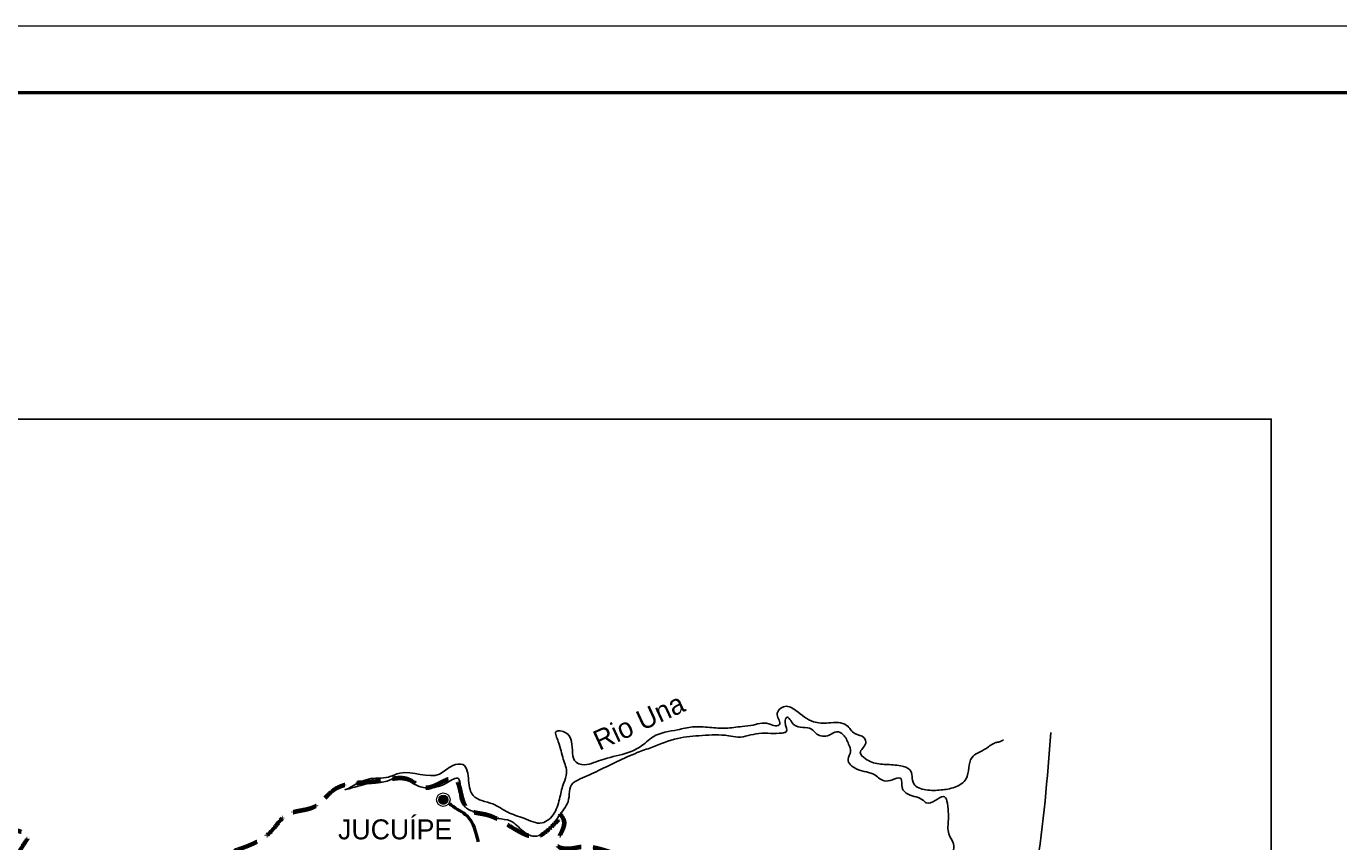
# Model space of a CAD drawing. Extents: x 512883 to 1063249, y 8784064 to 9081064.
# Drawn here: x 851806 to 950481, y 9019768 to 9081064 of the extents above; entities that cross this region are included whole.
import ezdxf

# ---------------------------------------------------------------- set-up
doc = ezdxf.new("R2010")
doc.units = 0
doc.header["$LTSCALE"] = 600
doc.linetypes.add('MEDIUM_DASHED', pattern=[4.5, 3, -1.5])
for name, color, linetype, lineweight in [('1', 7, 'Continuous', 25), ('10', 7, 'Continuous', 53), ('13', 7, 'Continuous', 90), ('3', 7, 'Continuous', 25), ('5', 7, 'Continuous', 13), ('60', 7, 'Continuous', 25), ('7', 7, 'Continuous', 13)]:
    doc.layers.add(name, color=color, linetype=linetype, lineweight=lineweight)

msp = doc.modelspace()

# ---------------------------------------------------------------- linework, layer by layer
at = {"layer": '1', "lineweight": 13}
for points in [[(512883.1, 8784063.9), (1063248.6, 8784063.9), (1063248.6, 9081063.9), (512883.1, 9081063.9)], [(537883.1, 9076063.9), (1058248.6, 9076063.9), (1058248.6, 8789063.9), (537883.1, 8789063.9)]]:
    msp.add_lwpolyline(points, close=True, dxfattribs=at)
at = {"layer": '1', "lineweight": 53}
msp.add_lwpolyline([(537883.1, 8789063.9), (1058248.6, 8789063.9), (1058248.6, 9076063.9), (537883.1, 9076063.9)], close=True, dxfattribs=at)
at = {"layer": '1'}
msp.add_lwpolyline([(566926, 9051542.3), (945407.2, 9051542.3), (945407.2, 8818457.9), (566926, 8818457.9)], close=True, dxfattribs=at)
at = {"layer": '10', "lineweight": 25}
msp.add_lwpolyline([(537883.1, 9076063.9), (1058248.6, 9076063.9), (1058248.6, 8789063.9), (537883.1, 8789063.9)], close=True, dxfattribs=at)
at = {"layer": '10'}
msp.add_spline([(885798.3, 9019767.7), (884973.2, 9021685), (883758, 9022515.8), (883651.9, 9022605.9)], degree=3, dxfattribs=at)
at = {"layer": '13', "linetype": 'MEDIUM_DASHED', "lineweight": 70}
for points in [[(829197.7, 9014555.7), (831473.6, 9016400), (832666.2, 9017154.5), (834733.9, 9017369.9), (835640, 9019042.3), (836236.9, 9019586.8), (837561.8, 9019737.1), (838427.1, 9019635.6), (839749.4, 9020015.5), (840270.1, 9020184.1), (841903.2, 9019730.3), (843435.9, 9019255.3), (844202.6, 9018986.5), (845489.1, 9018969.8), (846564, 9019912.3), (847141.3, 9020415), (847503.1, 9020416.2), (848201.5, 9020877.5), (849137.8, 9021631.8), (849378.7, 9021653.5), (851009.8, 9020657.6), (851917.3, 9020333.2), (851204.2, 9018711.4), (851722.8, 9017284.2), (851463.5, 9016311.1), (851528.3, 9016051.6), (853343.4, 9016311.1), (853862, 9014494.6), (854510.2, 9013456.6), (856519.7, 9014819), (859436.7, 9015467.7), (863390.8, 9016246.2), (864298.3, 9017478.8), (865141, 9018062.7), (866956, 9018906), (870290.9, 9020619.3), (871354.3, 9021775.5), (873540.1, 9022444.2), (874876.6, 9023632.2), (878429.5, 9024355.4), (880633.5, 9024420.3), (881745.7, 9023840.8), (883985, 9024525.5), (884931.5, 9022281.3), (886399.3, 9021809.7), (890479.7, 9020270.3), (891416.2, 9021016.7), (892059.7, 9021678.2)], [(896159.6, 9018825.1), (893440.4, 9019354.2), (892436.9, 9019225.7), (891730.7, 9019473.9), (891903.7, 9020184), (892232, 9021395.4), (891946.9, 9021863.4)]]:
    msp.add_spline(points, degree=3, dxfattribs=at)
at = {"layer": '3'}
msp.add_lwpolyline([(537883.1, 9076063.9), (1058248.6, 9076063.9), (1058248.6, 8789063.9), (537883.1, 8789063.9)], close=True, dxfattribs=at)
at = {"layer": '5'}
for p, q in [((882828.3, 9022937.2), (883493.1, 9022937.2)), ((882828.9, 9022907.2), (883492.8, 9022907.2)), ((882830.4, 9022967.2), (883491, 9022967.2)), ((882831.9, 9022877.2), (883489.5, 9022877.2)), ((882835.2, 9022997.2), (883486.2, 9022997.2)), ((882843.3, 9023027.2), (883478.1, 9023027.2)), ((882854.1, 9023057.2), (883467.3, 9023057.5)), ((882868.5, 9023087.2), (883453.2, 9023087.2)), ((882886.8, 9023117.2), (883434.9, 9023117.2)), ((882910.8, 9023147.2), (883411.2, 9023147.2)), ((882939.9, 9023177.2), (883381.5, 9023177.2)), ((882979.5, 9023207.2), (883341.9, 9023207.2)), ((883036.8, 9023237.2), (883284.6, 9023237.2)), ((882837.9, 9022847.2), (883483.5, 9022847.2)), ((882846.9, 9022817.2), (883474.5, 9022817.2)), ((882859.5, 9022787.2), (883462.2, 9022787.5)), ((882875.4, 9022757.2), (883446, 9022757.2)), ((882896.1, 9022727.2), (883425.6, 9022727.5)), ((882921.3, 9022696.9), (883400.4, 9022697.2)), ((882954.6, 9022667.2), (883366.8, 9022667.2)), ((882999.6, 9022637.2), (883321.8, 9022637.2)), ((883073.4, 9022607.2), (883247.7, 9022607.2))]:
    msp.add_line(p, q, dxfattribs=at)
for radius in [506.1, 332.9]:
    msp.add_circle((883160.8, 9022928.2), radius, dxfattribs=at)
at = {"layer": '60'}
for points in [[(875966.3, 9023742.7), (876845.3, 9024225.5), (877525.8, 9024478.1), (879031.6, 9024629.1), (879892.5, 9024924), (882868, 9024850.1), (883885.8, 9025500.3), (884628.7, 9025565.3), (885064, 9024377.3), (885172.1, 9023689), (885398, 9023251.5), (886872.3, 9022609.3), (888004.7, 9021986.9), (889215.7, 9021531.7), (890586.3, 9021181.4), (891502.7, 9021914.7), (891931.5, 9023126.5), (892221.1, 9024191.7), (892434.1, 9024922.8), (892181.4, 9025965.4), (891804.9, 9027299.7), (891635.8, 9028050.5), (892380.6, 9027948.5), (892879.8, 9026426.7), (893148.7, 9025739), (893572.6, 9025573.4), (895015.9, 9025911.9), (896839.5, 9026397.8), (897959.5, 9026902.2), (898936, 9027656.7), (900779.2, 9028184.3), (901902.4, 9028396.6), (903189.1, 9028359.1), (904395.7, 9028300.3), (905620.3, 9028429.5), (906463.2, 9028536.6), (907124.9, 9028684.8), (907789.2, 9028582.6), (908232.6, 9028479.7), (908412.5, 9028563.7), (908263.5, 9029314.5), (908839.4, 9029942.4), (909666.9, 9029632.1), (911002.8, 9028780.8), (912109.2, 9028700.9), (912872.7, 9028724.2), (913477.9, 9028517.5), (914107.9, 9027893.5), (914794.7, 9027582.7), (914919.9, 9027165.7), (914505.7, 9026454.8), (914872.3, 9026017.8), (915901.7, 9025624.6), (916987.9, 9025544.7), (917551.5, 9025463), (918238.1, 9025173.1), (918531, 9024130.6), (919440.5, 9023674.4), (920586.3, 9023657.3), (921609, 9023869.2), (922466.3, 9024498.1), (922890.9, 9026085.4), (923968.6, 9026777.6), (924687.3, 9027218.1), (924967.9, 9027281.6), (925287.9, 9027428.8)], [(875966.3, 9023742.7), (876845.3, 9024225.5), (877525.8, 9024478.1), (879031.6, 9024629.1), (879892.5, 9024924), (882868, 9024850.1), (883885.8, 9025500.3), (884628.7, 9025565.3), (885064, 9024377.3), (885172.1, 9023689), (885398, 9023251.5), (886872.3, 9022609.3), (888004.7, 9021986.9), (889215.7, 9021531.7), (890586.3, 9021181.4), (891502.7, 9021914.7), (891931.5, 9023126.5), (892221.1, 9024191.7), (892434.1, 9024922.8), (892181.4, 9025965.4), (891804.9, 9027299.7), (891635.8, 9028050.5), (892380.6, 9027948.5), (892879.8, 9026426.7), (893148.7, 9025739), (893572.6, 9025573.4), (895015.9, 9025911.9), (896839.5, 9026397.8), (897959.5, 9026902.2), (898936, 9027656.7), (900779.2, 9028184.3), (901902.4, 9028396.6), (903189.1, 9028359.1), (904395.7, 9028300.3), (905620.3, 9028429.5), (906463.2, 9028536.6), (907124.9, 9028684.8), (907789.2, 9028582.6), (908232.6, 9028479.7), (908412.5, 9028563.7), (908263.5, 9029314.5), (908839.4, 9029942.4), (909666.9, 9029632.1), (911002.8, 9028780.8), (912109.2, 9028700.9), (912872.7, 9028724.2), (913477.9, 9028517.5), (914107.9, 9027893.5), (914794.7, 9027582.7), (914919.9, 9027165.7), (914505.7, 9026454.8), (914872.3, 9026017.8), (915901.7, 9025624.6), (916987.9, 9025544.7), (917551.5, 9025463), (918238.1, 9025173.1), (918531, 9024130.6), (919440.5, 9023674.4), (920586.3, 9023657.3), (921609, 9023869.2), (922466.3, 9024498.1), (922890.9, 9026085.4), (923968.6, 9026777.6), (924687.3, 9027218.1), (924967.9, 9027281.6), (925287.9, 9027428.8)], [(921127.1, 9022010.4), (920752.4, 9023177.8), (919471.5, 9022693.7), (919268.6, 9022860), (918117.7, 9023336.3), (917650, 9023835.6), (917582.3, 9024503.2), (916418.4, 9024332.5), (915609.4, 9024789), (914258, 9025222.8), (913586.5, 9025971.9), (913781.2, 9026536), (913634.3, 9027099), (913224.5, 9027807.2), (912739.6, 9028035.1), (912159.5, 9027782.8), (911234.1, 9027863.3), (910848.1, 9028237.7), (909497.6, 9028588.1), (908989.1, 9029129.1), (908852.6, 9028753), (908941.1, 9028022.9), (908640.5, 9027938.4), (907776.5, 9027914.8), (906872.1, 9027911.8), (905307.5, 9027635.5), (904602.9, 9027737.6), (902613, 9027752), (900786.4, 9027537.4), (898824.2, 9026863.3), (897743.2, 9026463.3), (896223.2, 9025790.6), (894643.8, 9025034.2), (893284, 9024403.8), (892904.7, 9024173), (892538.3, 9022773.7), (891846.7, 9021707.2), (891432, 9021038), (889974.3, 9020177.7), (889166.2, 9020550.7), (888192.8, 9021340.6), (887266.2, 9021525.4), (886257.6, 9021856.1), (884906.2, 9022289.9), (884435.6, 9023039.7), (884425, 9023999.6), (884298.6, 9024520.9), (883418, 9024184.1), (882195.9, 9023825.4), (881794, 9023824.1), (880926.3, 9024134.3), (879634.7, 9024610.2), (878934.5, 9024315.7), (877950.4, 9024249.9), (876968.4, 9023996.3), (875826, 9023700.5), (875966.3, 9023742.7)], [(921127.1, 9022010.4), (920752.4, 9023177.8), (919471.5, 9022693.7), (919268.6, 9022860), (918117.7, 9023336.3), (917650, 9023835.6), (917582.3, 9024503.2), (916418.4, 9024332.5), (915609.4, 9024789), (914258, 9025222.8), (913586.5, 9025971.9), (913781.2, 9026536), (913634.3, 9027099), (913224.5, 9027807.2), (912739.6, 9028035.1), (912159.5, 9027782.8), (911234.1, 9027863.3), (910848.1, 9028237.7), (909497.6, 9028588.1), (908989.1, 9029129.1), (908852.6, 9028753), (908941.1, 9028022.9), (908640.5, 9027938.4), (907776.5, 9027914.8), (906872.1, 9027911.8), (905307.5, 9027635.5), (904602.9, 9027737.6), (902613, 9027752), (900786.4, 9027537.4), (898824.2, 9026863.3), (897743.2, 9026463.3), (896223.2, 9025790.6), (894643.8, 9025034.2), (893284, 9024403.8), (892904.7, 9024173), (892538.3, 9022773.7), (891846.7, 9021707.2), (891432, 9021038), (889974.3, 9020177.7), (889166.2, 9020550.7), (888192.8, 9021340.6), (887266.2, 9021525.4), (886257.6, 9021856.1), (884906.2, 9022289.9), (884435.6, 9023039.7), (884425, 9023999.6), (884298.6, 9024520.9), (883418, 9024184.1), (882195.9, 9023825.4), (881794, 9023824.1), (880926.3, 9024134.3), (879634.7, 9024610.2), (878934.5, 9024315.7), (877950.4, 9024249.9), (876968.4, 9023996.3), (875826, 9023700.5), (875966.3, 9023742.7)], [(928828.8, 9027989.5), (927727.3, 9017705.9), (905698.2, 8975836.8), (863108.4, 8926255), (823455.9, 8876673.2), (798489.5, 8846556.8), (787107.7, 8828193.2)], [(928828.8, 9027989.5), (927727.3, 9017705.9), (905698.2, 8975836.8), (863108.4, 8926255), (823455.9, 8876673.2), (798489.5, 8846556.8), (787107.7, 8828193.2)], [(901775.1, 8987223), (902699.2, 8987267.7), (903381.6, 8987353.4), (903745.9, 8987125), (904216, 8986417), (904742.9, 8986022.2), (904975.1, 8986836.8), (904846.2, 8987587.7), (905358.8, 8988486.7), (906193.7, 8989324.1), (906819.3, 8990912.1), (908413, 8994005.8), (909378, 8995803.6), (909823.6, 8997307.5), (910391.9, 8998624.1), (911240.2, 9000066.7), (912825.4, 9002116.9), (913573.4, 9003538.4), (914627.5, 9004543.5), (915816.5, 9006070.7), (916949.4, 9007222.1), (917364.1, 9007891.3), (917588.9, 9009373.6), (918101, 9010314.4), (918646, 9011923), (919238.3, 9012884.8), (919495.7, 9013240.4), (920353.7, 9013806.7), (920562, 9014955.1), (920543.8, 9016603.6), (920872.3, 9017794.2), (921207.5, 9018379.6), (921515.4, 9019611.8), (921165.5, 9020361.9), (921133.3, 9021447), (921127.1, 9022010.4)], [(901775.1, 8987223), (902699.2, 8987267.7), (903381.6, 8987353.4), (903745.9, 8987125), (904216, 8986417), (904742.9, 8986022.2), (904975.1, 8986836.8), (904846.2, 8987587.7), (905358.8, 8988486.7), (906193.7, 8989324.1), (906819.3, 8990912.1), (908413, 8994005.8), (909378, 8995803.6), (909823.6, 8997307.5), (910391.9, 8998624.1), (911240.2, 9000066.7), (912825.4, 9002116.9), (913573.4, 9003538.4), (914627.5, 9004543.5), (915816.5, 9006070.7), (916949.4, 9007222.1), (917364.1, 9007891.3), (917588.9, 9009373.6), (918101, 9010314.4), (918646, 9011923), (919238.3, 9012884.8), (919495.7, 9013240.4), (920353.7, 9013806.7), (920562, 9014955.1), (920543.8, 9016603.6), (920872.3, 9017794.2), (921207.5, 9018379.6), (921515.4, 9019611.8), (921165.5, 9020361.9), (921133.3, 9021447), (921127.1, 9022010.4)]]:
    msp.add_spline(points, degree=3, dxfattribs=at)
at = {"layer": '7', "lineweight": 25}
for points in [[(875966.3, 9023742.7), (876845.3, 9024225.5), (877525.8, 9024478.1), (879031.6, 9024629.1), (879892.5, 9024924), (882868, 9024850.1), (883885.8, 9025500.3), (884628.7, 9025565.3), (885064, 9024377.3), (885172.1, 9023689), (885398, 9023251.5), (886872.3, 9022609.3), (888004.7, 9021986.9), (889215.7, 9021531.7), (890586.3, 9021181.4), (891502.7, 9021914.7), (891931.5, 9023126.5), (892221.1, 9024191.7), (892434.1, 9024922.8), (892181.4, 9025965.4), (891804.9, 9027299.7), (891635.8, 9028050.5), (892380.6, 9027948.5), (892879.8, 9026426.7), (893148.7, 9025739), (893572.6, 9025573.4), (895015.9, 9025911.9), (896839.5, 9026397.8), (897959.5, 9026902.2), (898936, 9027656.7), (900779.2, 9028184.3), (901902.4, 9028396.6), (903189.1, 9028359.1), (904395.7, 9028300.3), (905620.3, 9028429.5), (906463.2, 9028536.6), (907124.9, 9028684.8), (907789.2, 9028582.6), (908232.6, 9028479.7), (908412.5, 9028563.7), (908263.5, 9029314.5), (908839.4, 9029942.4), (909666.9, 9029632.1), (911002.8, 9028780.8), (912109.2, 9028700.9), (912872.7, 9028724.2), (913477.9, 9028517.5), (914107.9, 9027893.5), (914794.7, 9027582.7), (914919.9, 9027165.7), (914505.7, 9026454.8), (914872.3, 9026017.8), (915901.7, 9025624.6), (916987.9, 9025544.7), (917551.5, 9025463), (918238.1, 9025173.1), (918531, 9024130.6), (919440.5, 9023674.4), (920586.3, 9023657.3), (921609, 9023869.2), (922466.3, 9024498.1), (922890.9, 9026085.4), (923968.6, 9026777.6), (924687.3, 9027218.1), (924967.9, 9027281.6), (925287.9, 9027428.8)], [(921127.1, 9022010.4), (920752.4, 9023177.8), (919471.5, 9022693.7), (919268.6, 9022860), (918117.7, 9023336.3), (917650, 9023835.6), (917582.3, 9024503.2), (916418.4, 9024332.5), (915609.4, 9024789), (914258, 9025222.8), (913586.5, 9025971.9), (913781.2, 9026536), (913634.3, 9027099), (913224.5, 9027807.2), (912739.6, 9028035.1), (912159.5, 9027782.8), (911234.1, 9027863.3), (910848.1, 9028237.7), (909497.6, 9028588.1), (908989.1, 9029129.1), (908852.6, 9028753), (908941.1, 9028022.9), (908640.5, 9027938.4), (907776.5, 9027914.8), (906872.1, 9027911.8), (905307.5, 9027635.5), (904602.9, 9027737.6), (902613, 9027752), (900786.4, 9027537.4), (898824.2, 9026863.3), (897743.2, 9026463.3), (896223.2, 9025790.6), (894643.8, 9025034.2), (893284, 9024403.8), (892904.7, 9024173), (892538.3, 9022773.7), (891846.7, 9021707.2), (891432, 9021038), (889974.3, 9020177.7), (889166.2, 9020550.7), (888192.8, 9021340.6), (887266.2, 9021525.4), (886257.6, 9021856.1), (884906.2, 9022289.9), (884435.6, 9023039.7), (884425, 9023999.6), (884298.6, 9024520.9), (883418, 9024184.1), (882195.9, 9023825.4), (881794, 9023824.1), (880926.3, 9024134.3), (879634.7, 9024610.2), (878934.5, 9024315.7), (877950.4, 9024249.9), (876968.4, 9023996.3), (875826, 9023700.5), (875966.3, 9023742.7)], [(901775.1, 8987223), (902699.2, 8987267.7), (903381.6, 8987353.4), (903745.9, 8987125), (904216, 8986417), (904742.9, 8986022.2), (904975.1, 8986836.8), (904846.2, 8987587.7), (905358.8, 8988486.7), (906193.7, 8989324.1), (906819.3, 8990912.1), (908413, 8994005.8), (909378, 8995803.6), (909823.6, 8997307.5), (910391.9, 8998624.1), (911240.2, 9000066.7), (912825.4, 9002116.9), (913573.4, 9003538.4), (914627.5, 9004543.5), (915816.5, 9006070.7), (916949.4, 9007222.1), (917364.1, 9007891.3), (917588.9, 9009373.6), (918101, 9010314.4), (918646, 9011923), (919238.3, 9012884.8), (919495.7, 9013240.4), (920353.7, 9013806.7), (920562, 9014955.1), (920543.8, 9016603.6), (920872.3, 9017794.2), (921207.5, 9018379.6), (921515.4, 9019611.8), (921165.5, 9020361.9), (921133.3, 9021447), (921127.1, 9022010.4)]]:
    msp.add_spline(points, degree=3, dxfattribs=at)

# ---------------------------------------------------------------- texts
at = {"layer": '5'}
msp.add_text('JUCUÍPE', height=1500, dxfattribs=at).set_placement((875249.5, 9019948.4))
at = {"layer": '60'}
msp.add_text('Rio Una', height=1500, rotation=24.792, dxfattribs=at).set_placement((894888.7, 9026598.9))
at = {"layer": '7'}
msp.add_text('Rio Una', height=1500, rotation=24.792, dxfattribs=at).set_placement((894888.7, 9026598.9))

doc.saveas('drawing.dxf')
